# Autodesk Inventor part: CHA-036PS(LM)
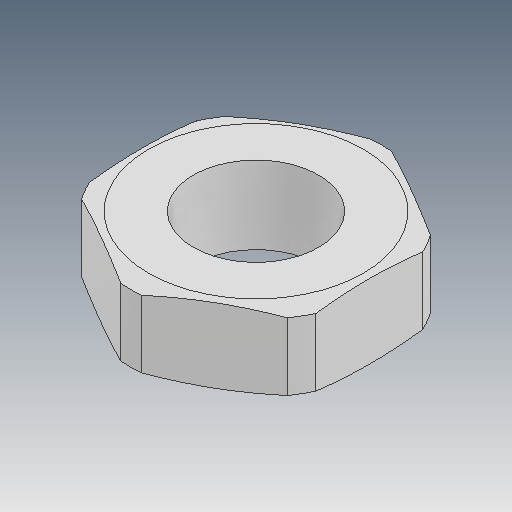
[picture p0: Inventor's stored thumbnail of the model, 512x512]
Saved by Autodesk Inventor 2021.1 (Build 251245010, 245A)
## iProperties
Created: 2021-05
Part Number: CHA-036PS(LM)
Material: Ogólny
Document SubType Name: Modeling
Designer: user
Density: 1 g/cm^3
Appearance: Domyślna
Author: user
Revision Number: ÈÎºÎ
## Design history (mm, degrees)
feature "M12x1.5 ÂÝÎÆ¿×1"
node "Bryła1"
